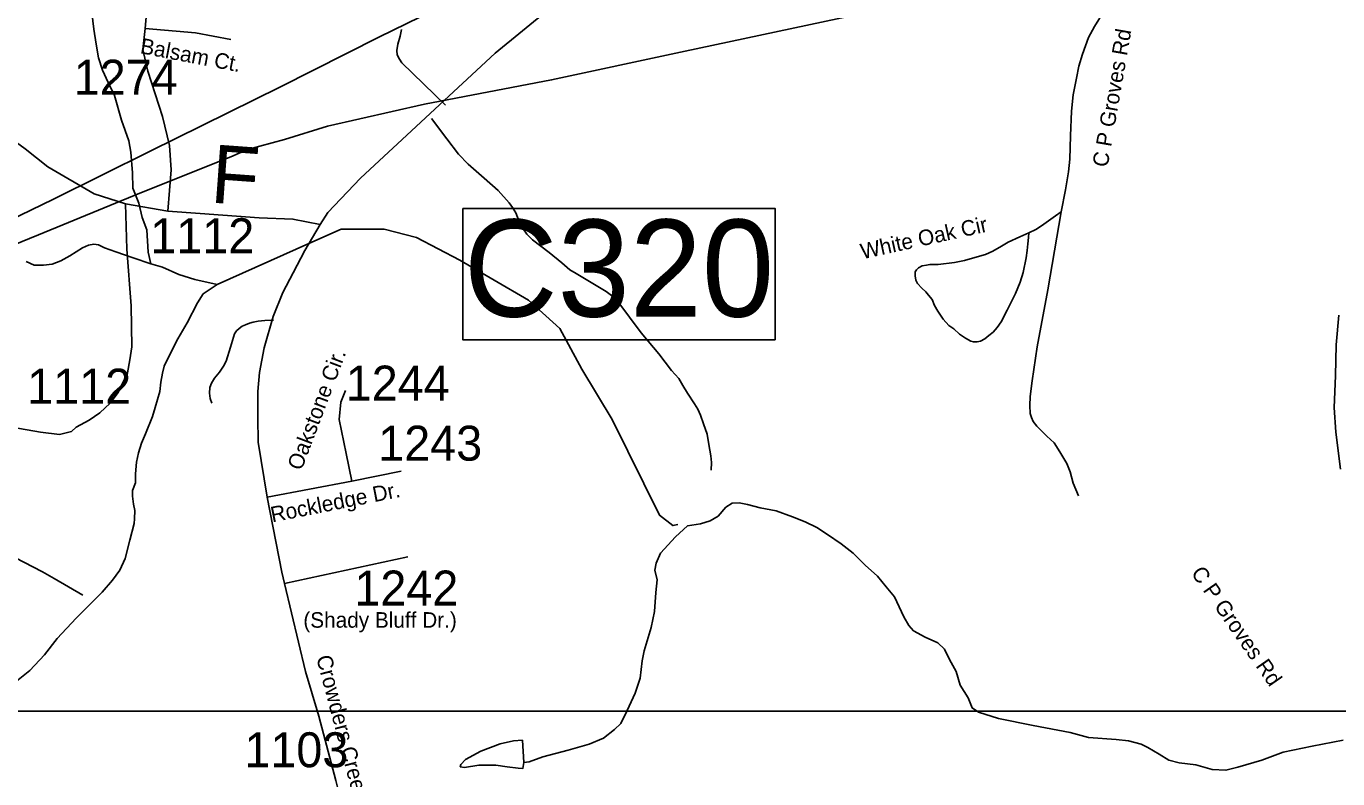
# Model space of a CAD drawing. Extents: x 1268485 to 1426702, y 514839 to 616766.
# Drawn here: x 1330300 to 1335842, y 529517 to 532695 of the extents above; entities that cross this region are included whole.
import ezdxf

# ---------------------------------------------------------------- set-up
doc = ezdxf.new("R2010")
doc.units = 0
for name, color, linetype in [('Old_Level_10', 7, 'Continuous'), ('Old_Level_11', 7, 'Continuous'), ('Old_Level_22', 7, 'Continuous'), ('Old_Level_31', 7, 'Continuous'), ('Old_Level_32', 7, 'Continuous'), ('Old_Level_35', 7, 'Continuous'), ('Old_Level_50', 7, 'Continuous'), ('Old_Level_56', 7, 'Continuous'), ('Old_Level_59', 7, 'Continuous'), ('Old_Level_62', 7, 'Continuous'), ('Old_Level_63', 7, 'Continuous'), ('Old_Level_8', 7, 'Continuous')]:
    doc.layers.add(name, color=color, linetype=linetype)

msp = doc.modelspace()

# ---------------------------------------------------------------- linework, layer by layer
at = {"layer": 'Old_Level_31'}
msp.add_line((1331493.819, 531777.695), (1331493.819, 531777.695), dxfattribs=at)
msp.add_lwpolyline([(1332144.662, 531926.143), (1333463.97, 531926.143), (1333463.97, 531370.916), (1332144.662, 531370.916), (1332144.662, 531926.143)], dxfattribs=at)
at = {"layer": 'Old_Level_32'}
for p, q in [((1330719.41, 531944.748), (1330898.163, 531914.904)), ((1331318.357, 530705.959), (1331675.456, 530773.702)), ((1331675.456, 530773.702), (1331884.882, 530815.389)), ((1331391.212, 530341.092), (1331912.205, 530453.803))]:
    msp.add_line(p, q, dxfattribs=at)
for points in [[(1329999.172, 535397.744), (1329986.166, 535272.825), (1329952.35, 535033.397), (1329864.459, 534455.251), (1329866.507, 534317.195), (1329871.71, 534255.776), (1329875.198, 534184.281), (1329888.623, 534080.061), (1329913.33, 533885.183), (1330035.07, 532916.54), (1330092.298, 532455.382), (1330105.305, 532403.332), (1330133.918, 532348.68), (1330243.172, 532215.954), (1330295.198, 532176.916), (1330391.445, 532101.444), (1330586.691, 531987.468), (1330719.41, 531944.748)], [(1330802.848, 532686.128), (1330825.67, 532946.677), (1330844.465, 533103.005)], [(1331542.551, 531857.583), (1331575.131, 531908.901), (1331712.314, 532054.012), (1332282.198, 532581.804), (1332512.509, 532770.862), (1332699.45, 532902.765), (1332825.023, 532968.07), (1332976.313, 533011.813), (1333081.026, 533030.052), (1333156.205, 533040.473), (1333239.438, 533043.079), (1333346.836, 533035.262), (1333422.015, 533030.052)], [(1330898.163, 531914.904), (1330912.931, 532089.471), (1330904.876, 532191.085), (1330875.342, 532313.543), (1330813.588, 532506.349), (1330792.108, 532597.541), (1330802.848, 532686.128)], [(1330802.848, 532686.128), (1331014.959, 532667.889), (1331165.316, 532639.229)], [(1329575.053, 531114.312), (1329732.295, 531094.8), (1330043.394, 531035.986), (1330360.749, 530981.336), (1330441.389, 530970.927), (1330490.814, 530983.939), (1330511.623, 531002.156), (1330566.251, 531030.784), (1330610.472, 531062.013), (1330654.694, 531103.653), (1330688.51, 531147.895), (1330727.529, 531231.175), (1330737.934, 531285.827), (1330745.739, 531340.478), (1330743.137, 531514.845), (1330724.928, 531754.272), (1330719.41, 531944.748)], [(1330898.163, 531914.904), (1331035.096, 531904.481), (1331284.796, 531886.243), (1331427.098, 531881.032), (1331542.551, 531857.583)], [(1331318.357, 530705.959), (1331280.768, 530937.847), (1331278.084, 531042.067), (1331278.48, 531153.1), (1331286.138, 531232.267), (1331304.972, 531337.089), (1331343.904, 531469.968), (1331385.037, 531570.19), (1331427.996, 531653.566), (1331476.612, 531748.533), (1331542.551, 531857.583)], [(1331675.456, 530773.702), (1331651.291, 530890.948), (1331621.757, 531034.25), (1331629.812, 531107.204), (1331648.606, 531156.708)], [(1331391.212, 530341.092), (1331379.61, 530389.43), (1331318.357, 530705.959)], [(1331496.518, 528581.021), (1331561.684, 528645.564), (1331591.762, 528677.334), (1331645.232, 528744.219), (1331668.625, 528791.038), (1331690.346, 528834.512), (1331703.714, 528877.987), (1331715.41, 529006.739), (1331710.398, 529075.296), (1331694.285, 529140.957), (1331685.251, 529189.161), (1331656.026, 529317.812), (1331608.253, 529509.066), (1331536.285, 529780.646), (1331480.271, 529970.066), (1331391.212, 530341.092)]]:
    msp.add_lwpolyline(points, dxfattribs=at)
at = {"layer": 'Old_Level_35'}
msp.add_line((1330417.492, 530362.19), (1330539.088, 530292.832), dxfattribs=at)
for points in [[(1334910.286, 532890.021), (1334899.521, 532840.194), (1334861.586, 532772.065), (1334814.014, 532694.197), (1334787.972, 532647.65), (1334763.161, 532577.317), (1334746.962, 532526.515), (1334737.222, 532476.739), (1334723.176, 532406.354), (1334716.614, 532337.201), (1334712.411, 532232.265), (1334709.13, 532133.789), (1334703.593, 532080.732), (1334691.7, 532005.068), (1334673.348, 531910.949)], [(1332071.75, 532361.448), (1331887.716, 532540.203), (1331877.258, 532555.992), (1331867.621, 532575.267), (1331865.878, 532592.799), (1331870.286, 532619.045), (1331880.744, 532653.237), (1331885.973, 532681.329)], [(1332012.08, 532305.879), (1332077.901, 532220.372), (1332127.011, 532154.602), (1332167.202, 532112.567), (1332235.279, 532053.255), (1332293.514, 532001.274), (1332340.881, 531949.55), (1332354.824, 531929.352), (1332368.87, 531907.514), (1332382.916, 531870.708), (1332400.346, 531839.13), (1332415.212, 531817.24), (1332438.998, 531792.685), (1332509.126, 531740.14), (1332562.542, 531695.439), (1332597.606, 531666.476), (1332623.853, 531650.738), (1332658.917, 531629.669), (1332708.847, 531600.757), (1332750.165, 531575.381), (1332778.154, 531554.312), (1332799.172, 531532.423), (1332899.033, 531400.933), (1332973.466, 531311.581), (1333026.985, 531241.505), (1333057.64, 531207.312), (1333074.25, 531178.4), (1333094.55, 531145.079), (1333124.282, 531100.378), (1333137.406, 531078.489), (1333149.606, 531052.191), (1333162.012, 531016.256), (1333176.878, 530971.554), (1333184.773, 530928.647), (1333192.667, 530880.459), (1333195.23, 530852.367), (1333194.41, 530820.789)], [(1334673.348, 531910.949), (1334649.665, 531894.699), (1334590.097, 531852.509), (1334565.286, 531837.387), (1334535.963, 531823.289)], [(1334673.348, 531910.949), (1334617.164, 531582.045), (1334571.745, 531340.801), (1334551.137, 531197.983), (1334542.217, 531130.675), (1334540.372, 531093.509), (1334542.217, 531059.624), (1334547.549, 531042.963), (1334555.238, 531025.124), (1334570.617, 531006.516), (1334586.919, 530989.24), (1334612.755, 530964.326), (1334643.103, 530935.106), (1334668.017, 530897.274), (1334697.134, 530848.574), (1334711.283, 530812.895), (1334724.201, 530765.323), (1334745.834, 530711.189)], [(1334535.963, 531823.289), (1334498.131, 531806.014), (1334449.534, 531783.253), (1334420.211, 531767.054), (1334384.532, 531745.421), (1334353.159, 531731.375), (1334307.74, 531718.354), (1334264.474, 531706.461), (1334222.234, 531696.772), (1334153.029, 531689.185), (1334118.375, 531689.185), (1334104.124, 531686.314)], [(1334218.953, 531416.568), (1334242.841, 531394.884), (1334268.78, 531377.608), (1334291.541, 531365.664), (1334302.512, 531361.768), (1334317.583, 531362.127), (1334332.654, 531365.664), (1334349.879, 531375.455), (1334367.205, 531388.425), (1334385.66, 531403.547), (1334402.885, 531422.976), (1334419.084, 531446.813), (1334445.125, 531495.513), (1334479.779, 531565.795), (1334499.259, 531614.495), (1334512.28, 531654.583), (1334525.096, 531717.329), (1334529.504, 531748.702), (1334531.657, 531776.794), (1334534.836, 531802.733), (1334535.963, 531823.289)], [(1334104.124, 531686.314), (1334085.977, 531682.675), (1334070.598, 531675.088), (1334061.268, 531666.424), (1334056.757, 531657.812), (1334055.629, 531640.485), (1334058.705, 531622.645), (1334066.497, 531609.112), (1334083.721, 531589.632), (1334101.15, 531573.382), (1334113.043, 531559.336), (1334128.115, 531540.932), (1334137.855, 531516.07), (1334152.003, 531491.207), (1334174.662, 531457.63), (1334198.55, 531431.691), (1334218.953, 531416.568)], [(1331344.328, 531454.452), (1331307.828, 531452.76), (1331280.761, 531449.736), (1331259.641, 531445.327), (1331243.032, 531440.867), (1331226.218, 531434.562), (1331212.274, 531427.898), (1331199.253, 531418.619), (1331188.078, 531408.263), (1331179.671, 531396.575), (1331162.959, 531339.623), (1331145.53, 531280.926), (1331134.149, 531259.857), (1331116.515, 531233.559), (1331095.497, 531208.184), (1331082.374, 531187.115), (1331076.222, 531168.763), (1331074.479, 531145.079), (1331077.965, 531123.19), (1331085.039, 531103.864)], [(1329813.204, 530643.266), (1329942.079, 530592.566), (1330135.956, 530510.7), (1330368.28, 530390.334), (1330417.492, 530362.19)]]:
    msp.add_lwpolyline(points, dxfattribs=at)
at = {"layer": 'Old_Level_50'}
msp.add_line((1331493.819, 531777.695), (1331493.819, 531777.695), dxfattribs=at)
at = {"layer": 'Old_Level_56'}
for points in [[(1329118.961, 531320.629), (1329153.325, 531337.946), (1329572.161, 531548.823), (1330033.443, 531780.856), (1330415.714, 531964.455), (1330824.389, 532167.532), (1331374.718, 532439.592), (1331789.518, 532648.748), (1332141.386, 532822.954), (1332432.851, 532968.561), (1332813.287, 533160.4), (1333068.191, 533288.934), (1333201.801, 533355.879), (1333252.246, 533376.873), (1333328.569, 533391.145), (1333640.627, 533476.308), (1334093.454, 533596.455), (1334528.16, 533710.965), (1335244.8, 533905.241), (1336049.97, 534123.747)], [(1336071.126, 533812.97), (1335762.142, 533681.723), (1335491.563, 533569.713), (1335118.051, 533413.752), (1334736.302, 533256.156), (1334691.938, 533239.041), (1334675.614, 533223.362), (1334508.153, 533075.059), (1334293.923, 532889.679), (1334220.594, 532825.323), (1334184.391, 532816.047), (1333746.29, 532731.62), (1333064.654, 532586.463), (1332519.83, 532468.567), (1331983.324, 532366.312), (1331573.059, 532273.121), (1331391.849, 532217.139), (1331234.722, 532174.679), (1331164.074, 532144.086), (1330780.407, 531990.53), (1330352.455, 531813.854), (1329884.017, 531623.986)]]:
    msp.add_lwpolyline(points, dxfattribs=at)
at = {"layer": 'Old_Level_59'}
for points in [[(1333052.675, 530591.185), (1333032.419, 530585.749), (1332975.414, 530629.63), (1332775.386, 531034.095), (1332647.434, 531246.785), (1332555.186, 531418.152), (1332422.512, 531537.635), (1332132.445, 531706.819), (1331949.734, 531802.803), (1331812.639, 531838.205), (1331631.319, 531838.205), (1331493.819, 531777.695), (1331106.262, 531605.165)], [(1330826.058, 531691.235), (1330752.547, 531717.329), (1330679.036, 531742.601), (1330631.464, 531759.979), (1330605.73, 531771.975), (1330585.737, 531774.846), (1330563.592, 531771.206), (1330537.345, 531759.415), (1330484.647, 531725.171), (1330446.097, 531703.795), (1330409.803, 531690.569), (1330373.714, 531685.596), (1330333.728, 531686.366), (1330299.895, 531701.027)], [(1331106.262, 531605.165), (1331012.758, 531625.106), (1330945.194, 531646.996), (1330875.681, 531677.907), (1330826.058, 531691.235)], [(1335845.733, 531474.495), (1335834.968, 531349.158), (1335832.098, 531218.744), (1335827.176, 531085.101), (1335832.918, 530980.73), (1335853.423, 530824.429)], [(1335864.188, 529679.419), (1335733.673, 529654.145), (1335610.949, 529628.719), (1335520.213, 529595.245), (1335419.533, 529565.307), (1335369.192, 529552.337), (1335311.163, 529555.157), (1335241.65, 529575.457), (1335171.83, 529584.223), (1335128.051, 529595.757), (1335086.528, 529620.414), (1335039.161, 529649.276), (1335011.377, 529662.142), (1334957.755, 529677.163), (1334905.877, 529682.289), (1334787.972, 529691.26), (1334710.463, 529712.483), (1334555.033, 529741.908), (1334407.601, 529771.128), (1334324.145, 529797.426), (1334296.462, 529816.034), (1334279.341, 529858.224), (1334246.635, 529911.383), (1334229.821, 529969.208), (1334200.908, 530019.805), (1334179.89, 530064.557), (1334152.516, 530091.368), (1334098.997, 530114.59), (1334049.477, 530141.862), (1334029.997, 530164.418), (1334008.774, 530200.097), (1333968.687, 530285.45), (1333933.52, 530327.998), (1333896.611, 530373.058), (1333845.45, 530418.426), (1333794.598, 530469.484), (1333743.437, 530508.29), (1333686.227, 530547.967), (1333640.911, 530578.469), (1333591.391, 530601.589), (1333537.872, 530623.171), (1333468.36, 530648.392), (1333400.59, 530660.439), (1333346.969, 530675.459), (1333313.033, 530681.866), (1333282.993, 530680.841), (1333256.643, 530663.309), (1333223.733, 530626.246), (1333189.284, 530606.407), (1333149.094, 530593.284), (1333094.857, 530584.518)]]:
    msp.add_lwpolyline(points, dxfattribs=at)
at = {"layer": 'Old_Level_62'}
for points in [[(1330826.058, 531691.235), (1330815.191, 531741.525), (1330809.244, 531836.002), (1330790.277, 531888.085), (1330775.616, 531948.268), (1330751.009, 532011.168), (1330748.446, 532076.836), (1330742.397, 532163.163), (1330733.375, 532211.76), (1330703.232, 532298.497), (1330673.602, 532403.33), (1330646.74, 532458.028), (1330621.929, 532510.213), (1330605.115, 532562.246), (1330596.298, 532619.045), (1330585.737, 532683.277), (1330577.228, 532753.2)], [(1331106.262, 531605.165), (1331047.31, 531564.513), (1331024.446, 531527.245), (1330980.565, 531441.944), (1330941.093, 531374.635), (1330914.026, 531323.474), (1330882.55, 531260.113), (1330875.886, 531229.868), (1330869.017, 531192.241), (1330864.198, 531152.153), (1330844.718, 531084.435), (1330833.85, 531046.911), (1330804.22, 530973.656), (1330787.304, 530933.773), (1330774.488, 530893.788), (1330765.568, 530853.803), (1330762.39, 530804.59), (1330761.672, 530766.04), (1330748.959, 530734.309), (1330748.446, 530710.523), (1330753.675, 530675.92), (1330759.109, 530650.391), (1330758.289, 530614.302), (1330755.828, 530594.668), (1330738.296, 530524.438), (1330718.611, 530446.877), (1330695.44, 530397.306), (1330664.58, 530356.039), (1330621.417, 530305.237), (1330570.359, 530254.538), (1330510.996, 530195.022), (1330430.923, 530108.848), (1330377.507, 530040.156), (1330315.889, 529973.258), (1330258.987, 529928.454)], [(1333094.857, 530584.518), (1333043.697, 530537.972), (1332980.233, 530469.484), (1332961.266, 530428.012), (1332956.55, 530397.716), (1332965.674, 530357.321), (1332960.548, 530303.289), (1332954.807, 530223.78), (1332941.273, 530155.96), (1332911.028, 530056.458), (1332902.211, 530014.781), (1332894.521, 529941.065), (1332873.196, 529877.499), (1332839.465, 529804.295), (1332812.398, 529750.725), (1332785.741, 529724.991), (1332738.887, 529688.184), (1332678.294, 529663.117), (1332589.609, 529637.024), (1332483.084, 529609.598), (1332424.542, 529588.631), (1332402.499, 529585.812)], [(1332402.499, 529585.812), (1332396.552, 529679.469), (1332358.413, 529676.138), (1332302.126, 529664.142), (1332221.438, 529633.743), (1332156.641, 529597.295), (1332136.136, 529577.2), (1332133.983, 529567.408), (1332151.823, 529564.589), (1332212.108, 529574.022), (1332284.184, 529574.227), (1332331.961, 529566.691), (1332377.995, 529561.667), (1332397.885, 529559.616), (1332402.499, 529585.812)]]:
    msp.add_lwpolyline(points, dxfattribs=at)
at = {"layer": 'Old_Level_63'}
for points in [[(1305516.95, 558564.883), (1305516.95, 529802.059), (1368033.021, 529802.059), (1368033.021, 573241.255), (1305516.95, 573241.255), (1305516.95, 558564.883)], [(1305516.95, 529802.059), (1368033.021, 529802.059), (1368033.021, 517504.204), (1305516.95, 517504.204), (1305516.95, 529802.059)]]:
    msp.add_lwpolyline(points, dxfattribs=at)

# ---------------------------------------------------------------- texts
at = {"layer": 'Old_Level_10'}
for s, height, rotation, p in [('C P Groves Rd', 65.61665, 80.127922, (1334868.926, 532097.051)), ('White Oak Cir', 65.61666, 12.467381, (1333833.15, 531710.837)), ('C P Groves Rd', 65.61666, 304.826258, (1335219.37, 530385.59))]:
    msp.add_text(s, height=height, rotation=rotation, dxfattribs=at).set_placement(p)
at = {"layer": 'Old_Level_11'}
for s, height, rotation, p in [('Balsam Ct.', 65.6167, 349.208264, (1330778.528, 532581.796)), ('Oakstone Cir.', 65.61666, 69.210864, (1331462.58, 530815.14)), ('Rockledge Dr.', 65.61666, 11.257794, (1331339.714, 530599.049)), ('Crowders Creek Rd.', 65.61666, 284.842161, (1331524.809, 530029.692))]:
    msp.add_text(s, height=height, rotation=rotation, dxfattribs=at).set_placement(p)
msp.add_text('(Shady Bluff Dr.)', height=65.61666, dxfattribs=at).set_placement((1331470.981, 530154.715))
at = {"layer": 'Old_Level_22'}
msp.add_text('F', height=246.062, rotation=355.822522, dxfattribs=at).set_placement((1331074.955, 531950.927))
at = {"layer": 'Old_Level_31'}
msp.add_text('C320', height=410.1042, dxfattribs=at).set_placement((1332149.196, 531468.627))
at = {"layer": 'Old_Level_8'}
for s, p in [('1274', (1330500.751, 532406.272)), ('1112', (1330824.434, 531736.63)), ('1112', (1330304.295, 531101.105)), ('1244', (1331650.25, 531114.117)), ('1243', (1331787.401, 530860.382)), ('1242', (1331686.699, 530248.348)), ('1103', (1331221.83, 529565.224))]:
    msp.add_text(s, height=147.6375, dxfattribs=at).set_placement(p)

doc.saveas('drawing.dxf')
